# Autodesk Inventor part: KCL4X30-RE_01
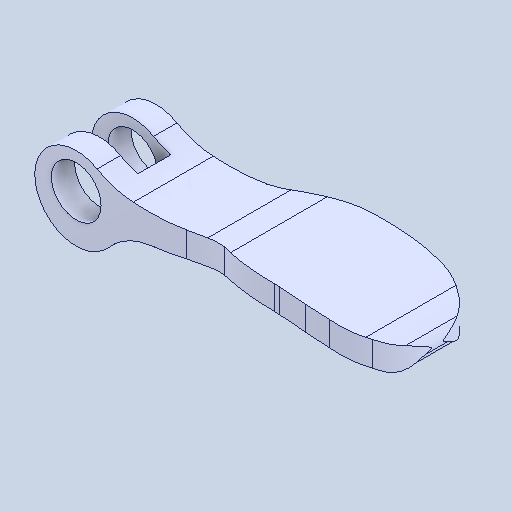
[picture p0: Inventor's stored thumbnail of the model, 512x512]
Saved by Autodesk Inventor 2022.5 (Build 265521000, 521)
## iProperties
Created: 2024-08
Part Number: KCL4X30-RE_01
Material: 一般
Document SubType Name: Modeling
Designer: ImaoCorp
Density: 1 g/cm^3
Appearance: 既定
Author: ImaoCorp
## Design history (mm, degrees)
feature "KCL4X30-RE_01"
node "ソリッド1"
